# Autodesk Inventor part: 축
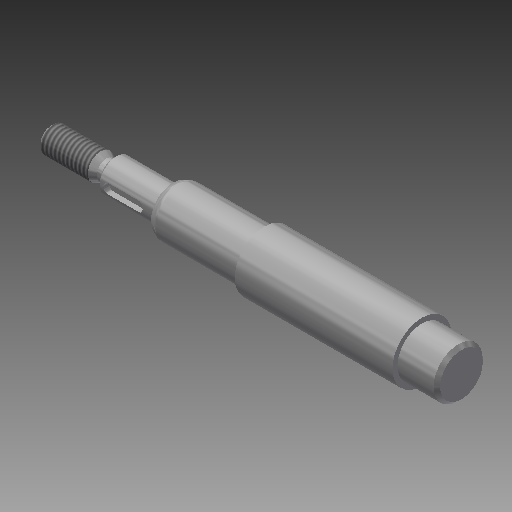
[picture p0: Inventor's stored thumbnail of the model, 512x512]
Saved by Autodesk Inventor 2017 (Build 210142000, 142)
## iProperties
Created: 2015-11
Part Number: 축
Material: 강철, 연강
Document SubType Name: Modeling
Designer: mduedu
Density: 1 g/cm^3
Appearance: 강철
Author: mduedu
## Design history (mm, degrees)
sketch "스케치1"
  geometry: L1 (-89, 0)-(89, 0); L2 (-89, 0)-(-89, 4); L3 (-89, 4)-(-73.732, 4); L4 (-73.732, 4)-(-72, 3); L5 (-72, 3)-(-70, 3); L6 (-70, 3)-(-70, 5); L7 (-70, 5)-(-52, 5); L8 (-52, 5)-(-52, 6.55); L9 (-50.355, 7.5)-(-24, 7.5); L10 (-24, 7.5)-(-24, 9); L11 (0, 0)-(0, 9); L12 (89, 4)-(73.732, 4); L13 (73.732, 4)-(72, 3); L14 (72, 3)-(70, 3); L15 (70, 3)-(70, 5); L16 (70, 5)-(52, 5); L17 (24, 7.5)-(24, 9); L18 (89, 0)-(89, 4); L19 (-24, 9)-(24, 9); L20 (-52, 6.55)-(-50.355, 7.5); L21 (50.355, 7.5)-(24, 7.5); L22 (52, 6.55)-(50.355, 7.5); L23 (52, 5)-(52, 6.55); 1 further point
  constraints: 46 end point, 10 symmetric about line, 6 perpendicular, 5 parallel, 2 midpoint, 1 coincident, 1 horizontal
  dimensions: "d0" = 178 distance of L1.start L1.end (derived); "d1" = 8 diameter of L3 L1; "d2" = 30 deg angle of L4 L5; "d3" = 6 diameter of L5 L1; "d4" = 10 diameter of L7 L1; "d5" = 15 diameter of L9 L1; "d6" = 18 diameter of L19 L1; "d8" = 18 distance of L6.end L7.end; "d9" = 48 distance of L10.end L17.end; "d10" = 2 distance of L4.end L5.end; "d11" = 17 distance from line of L4.end L2; "d16" = 13.1 diameter of L8.end L1; "d17" = 30 deg angle of L20 L9; "d18" = 28 distance between parallel lines of L10 L8
revolve "회전1" sketch "스케치1" stored, may be unused: angle "d12" = 90 deg
chamfer "모따기1" distance "d13" = 1; stored, may be unused: second distance "d14" = 2, angle "d15" = 45 deg
fillet "모깎기1" dims "d19" = 4, "d20" = 0.5
node "작업 평면1"
sketch "스케치2" dims "d23" = 12
  geometry: L1 (-5.5, 1.5)-(3.5, 1.5); L2 (3.5, 1.5)-(3.5, -1.5); L3 (3.5, -1.5)-(-5.5, -1.5); L4 (-5.5, -1.5)-(-5.5, 1.5); L5 (-9, -4)-(-9, 4) reference; 3 further points
  constraints: 8 end point, 2 midpoint, 2 parallel, 2 vertical alignment, 1 horizontal, 1 perpendicular, 4 other
  dimensions: "d21" = 3 distance between parallel lines of L3 L1; "d24" = 2 dimension on L5
extrude "돌출1" cut sketch "스케치2" distance "d25" = 1.8; taper "d26" = 0 deg
feature "스레드1" dims "d27" = 10, "d28" = 0
feature "스레드2" dims "d29" = 10, "d30" = 0
chamfer "모따기2" distance "d31" = 1; stored, may be unused: second distance "d32" = 2, angle "d33" = 45 deg
node "작업 평면2"
sketch "스케치3"
  geometry: C1 r 7.5 at (0, 0) reference; 1 further point
extrude "돌출2" cut sketch "스케치3" stored distance "d36" = 10; taper "d37" = 0 deg
chamfer "모따기3" distance "d38" = 1; stored, may be unused: second distance "d39" = 2, angle "d40" = 45 deg
node "솔리드1"
mirror "대칭1"
node "절단 모서리 투영1"
other parameters: "d35" = 12
